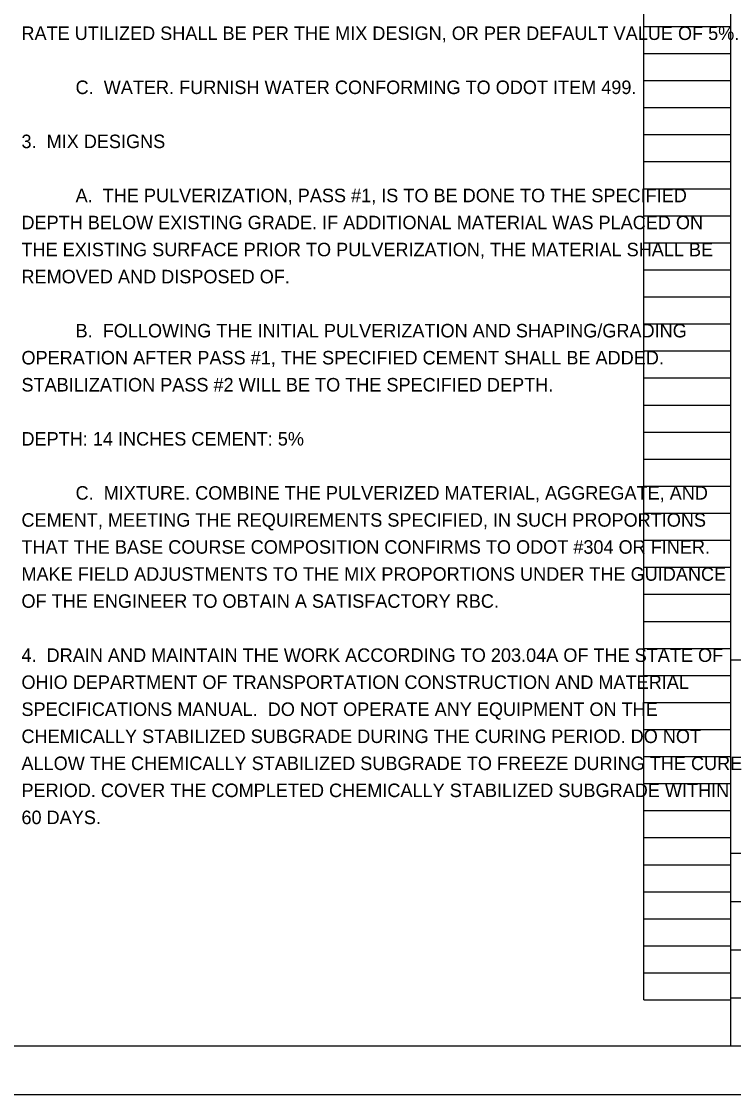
# Model space of a CAD drawing. Extents: x 0 to 46.4, y 0 to 22.
# Drawn here: x 24.66 to 32.03, y 0 to 11.11 of the extents above; entities that cross this region are included whole.
import ezdxf

# ---------------------------------------------------------------- set-up
doc = ezdxf.new("R2010")
doc.units = 0
for name, color, linetype in [('SH_Border', 7, 'Continuous'), ('SH_Cut_Line', 7, 'Continuous'), ('SH_Data', 7, 'Continuous'), ('SH_Text', 7, 'Continuous')]:
    doc.layers.add(name, color=color, linetype=linetype)

msp = doc.modelspace()

# ---------------------------------------------------------------- linework, layer by layer
at = {"layer": 'SH_Border'}
for p, q in [((32, 0.5), (32, 21.5)), ((32, 4.5), (33.5, 4.5)), ((32, 2.5), (33.5, 2.5)), ((32, 2), (33.5, 2)), ((32, 1.5), (33.5, 1.5)), ((32, 1), (33.5, 1))]:
    msp.add_line(p, q, dxfattribs=at)
msp.add_lwpolyline([(1.5, 21.5), (33.5, 21.5), (33.5, 0.5), (1.5, 0.5)], close=True, dxfattribs=at)
at = {"layer": 'SH_Cut_Line'}
msp.add_lwpolyline([(0, 0), (34, 0), (34, 22), (0, 22)], close=True, dxfattribs=at)
at = {"layer": 'SH_Data'}
for p, q in [((31.1, 0.98), (31.1, 21.14)), ((32, 0.98), (32, 21.14)), ((31.1, 11.06), (32, 11.06)), ((31.1, 10.78), (32, 10.78)), ((31.1, 10.5), (32, 10.5)), ((31.1, 10.22), (32, 10.22)), ((31.1, 9.94), (32, 9.94)), ((31.1, 9.66), (32, 9.66)), ((31.1, 9.38), (32, 9.38)), ((31.1, 9.1), (32, 9.1)), ((31.1, 8.82), (32, 8.82)), ((31.1, 8.54), (32, 8.54)), ((31.1, 8.26), (32, 8.26)), ((31.1, 7.98), (32, 7.98)), ((31.1, 7.7), (32, 7.7)), ((31.1, 7.42), (32, 7.42)), ((31.1, 7.14), (32, 7.14)), ((31.1, 6.86), (32, 6.86)), ((31.1, 6.58), (32, 6.58)), ((31.1, 6.3), (32, 6.3)), ((31.1, 6.02), (32, 6.02)), ((31.1, 5.74), (32, 5.74)), ((31.1, 5.46), (32, 5.46)), ((31.1, 5.18), (32, 5.18)), ((31.1, 4.9), (32, 4.9)), ((31.1, 4.62), (32, 4.62)), ((31.1, 4.34), (32, 4.34)), ((31.1, 4.06), (32, 4.06)), ((31.1, 3.78), (32, 3.78)), ((31.1, 3.5), (32, 3.5)), ((31.1, 3.22), (32, 3.22)), ((31.1, 2.94), (32, 2.94)), ((31.1, 2.66), (32, 2.66)), ((31.1, 2.38), (32, 2.38)), ((31.1, 2.1), (32, 2.1)), ((31.1, 1.82), (32, 1.82)), ((31.1, 1.54), (32, 1.54)), ((31.1, 1.26), (32, 1.26)), ((31.1, 0.98), (32, 0.98))]:
    msp.add_line(p, q, dxfattribs=at)

# ---------------------------------------------------------------- texts
at = {"layer": 'SH_Text'}
for s, p in [('RATE UTILIZED SHALL BE PER THE MIX DESIGN, OR PER DEFAULT VALUE OF 5%.', (24.66, 10.92)), ('C.  WATER. FURNISH WATER CONFORMING TO ODOT ITEM 499.', (25.22, 10.36)), ('3.  MIX DESIGNS', (24.66, 9.8)), ('A.  THE PULVERIZATION, PASS #1, IS TO BE DONE TO THE SPECIFIED ', (25.22, 9.24)), ('DEPTH BELOW EXISTING GRADE. IF ADDITIONAL MATERIAL WAS PLACED ON ', (24.66, 8.96)), ('THE EXISTING SURFACE PRIOR TO PULVERIZATION, THE MATERIAL SHALL BE ', (24.66, 8.68)), ('REMOVED AND DISPOSED OF.', (24.66, 8.4)), ('B.  FOLLOWING THE INITIAL PULVERIZATION AND SHAPING/GRADING ', (25.22, 7.84)), ('OPERATION AFTER PASS #1, THE SPECIFIED CEMENT SHALL BE ADDED. ', (24.66, 7.56)), ('STABILIZATION PASS #2 WILL BE TO THE SPECIFIED DEPTH.', (24.66, 7.28)), ('DEPTH: 14 INCHES CEMENT: 5%', (24.66, 6.72)), ('C.  MIXTURE. COMBINE THE PULVERIZED MATERIAL, AGGREGATE, AND ', (25.22, 6.16)), ('CEMENT, MEETING THE REQUIREMENTS SPECIFIED, IN SUCH PROPORTIONS ', (24.66, 5.88)), ('THAT THE BASE COURSE COMPOSITION CONFIRMS TO ODOT #304 OR FINER. ', (24.66, 5.6)), ('MAKE FIELD ADJUSTMENTS TO THE MIX PROPORTIONS UNDER THE GUIDANCE ', (24.66, 5.32)), ('OF THE ENGINEER TO OBTAIN A SATISFACTORY RBC.', (24.66, 5.04)), ('4.  DRAIN AND MAINTAIN THE WORK ACCORDING TO 203.04A OF THE STATE OF ', (24.66, 4.48)), ('OHIO DEPARTMENT OF TRANSPORTATION CONSTRUCTION AND MATERIAL ', (24.66, 4.2)), ('SPECIFICATIONS MANUAL.  DO NOT OPERATE ANY EQUIPMENT ON THE ', (24.66, 3.92)), ('CHEMICALLY STABILIZED SUBGRADE DURING THE CURING PERIOD. DO NOT ', (24.66, 3.64)), ('ALLOW THE CHEMICALLY STABILIZED SUBGRADE TO FREEZE DURING THE CURE ', (24.66, 3.36)), ('PERIOD. COVER THE COMPLETED CHEMICALLY STABILIZED SUBGRADE WITHIN ', (24.66, 3.08)), ('60 DAYS.', (24.66, 2.8))]:
    msp.add_text(s, height=0.14, dxfattribs=at).set_placement(p)

doc.saveas('drawing.dxf')
